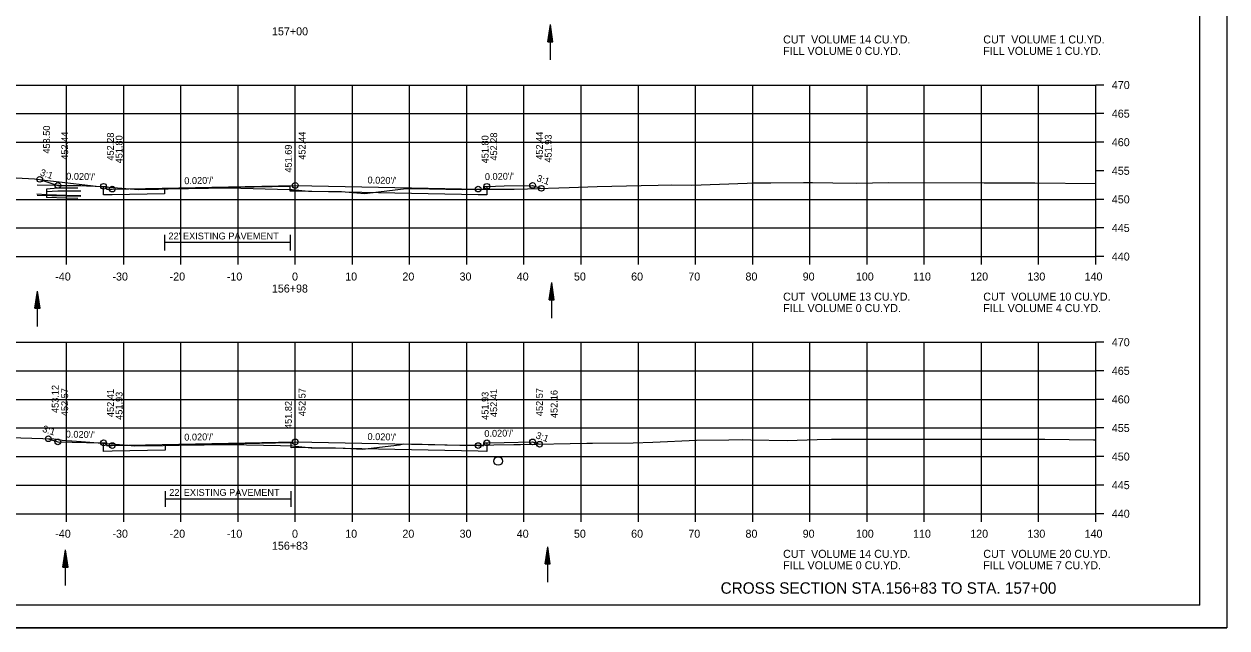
# Model space of a CAD drawing. Extents: x 1538688 to 1540766, y 656250 to 671912.
# Drawn here: x 1538810.8 to 1539021.1, y 666364.8 to 666470.4 of the extents above; entities that cross this region are included whole.
import ezdxf

# ---------------------------------------------------------------- set-up
doc = ezdxf.new("R2010")
doc.units = 0
for name, color, linetype in [('15', 7, 'Continuous'), ('18', 7, 'Continuous'), ('20', 7, 'Continuous'), ('22', 7, 'Continuous'), ('26', 7, 'Continuous'), ('39', 7, 'Continuous'), ('41', 7, 'Continuous'), ('42', 7, 'Continuous'), ('7', 7, 'Continuous'), ('Borings', 7, 'Continuous'), ('Horizontal Alignment', 7, 'Continuous'), ('RipRap', 7, 'Continuous'), ('Wall Heights', 7, 'Continuous')]:
    doc.layers.add(name, color=color, linetype=linetype)

msp = doc.modelspace()

# ---------------------------------------------------------------- linework, layer by layer
at = {"layer": '15'}
for p, q in [((1538902.35, 666467.34), (1538902.8, 666470.34)), ((1538903.25, 666467.34), (1538902.8, 666470.34)), ((1538902.43, 666467.34), (1538902.8, 666469.84)), ((1538902.5, 666467.34), (1538902.8, 666469.33)), ((1538902.58, 666467.34), (1538902.8, 666468.83)), ((1538902.66, 666467.34), (1538902.8, 666468.32)), ((1538903.18, 666467.34), (1538902.8, 666469.84)), ((1538903.1, 666467.34), (1538902.8, 666469.33)), ((1538903.03, 666467.34), (1538902.8, 666468.83)), ((1538902.95, 666467.34), (1538902.8, 666468.32)), ((1538902.35, 666467.34), (1538903.25, 666467.34)), ((1538902.73, 666467.34), (1538902.8, 666467.82)), ((1538902.87, 666467.34), (1538902.8, 666467.82)), ((1538902.58, 666422.2), (1538903.03, 666425.2)), ((1538902.66, 666422.2), (1538903.03, 666424.7)), ((1538902.73, 666422.2), (1538903.03, 666424.18)), ((1538903.48, 666422.2), (1538903.03, 666425.2)), ((1538903.41, 666422.2), (1538903.03, 666424.7)), ((1538903.33, 666422.2), (1538903.03, 666424.18)), ((1538812.67, 666420.73), (1538813.12, 666423.73)), ((1538812.75, 666420.73), (1538813.12, 666423.23)), ((1538812.83, 666420.73), (1538813.12, 666422.71)), ((1538812.9, 666420.73), (1538813.12, 666422.21)), ((1538812.98, 666420.73), (1538813.12, 666421.7)), ((1538813.57, 666420.73), (1538813.12, 666423.73)), ((1538813.5, 666420.73), (1538813.12, 666423.23)), ((1538813.42, 666420.73), (1538813.12, 666422.71)), ((1538813.35, 666420.73), (1538813.12, 666422.21)), ((1538813.27, 666420.73), (1538813.12, 666421.7)), ((1538902.58, 666422.2), (1538903.48, 666422.2)), ((1538902.81, 666422.2), (1538903.03, 666423.68)), ((1538902.89, 666422.2), (1538903.03, 666423.17)), ((1538902.96, 666422.2), (1538903.03, 666422.67)), ((1538903.26, 666422.2), (1538903.03, 666423.68)), ((1538903.18, 666422.2), (1538903.03, 666423.17)), ((1538903.1, 666422.2), (1538903.03, 666422.67)), ((1538812.67, 666420.73), (1538813.57, 666420.73)), ((1538813.05, 666420.73), (1538813.12, 666421.2)), ((1538813.19, 666420.73), (1538813.12, 666421.2)), ((1538817.56, 666375.43), (1538818.01, 666378.43)), ((1538817.64, 666375.43), (1538818.01, 666377.93)), ((1538818.46, 666375.43), (1538818.01, 666378.43)), ((1538818.39, 666375.43), (1538818.01, 666377.93)), ((1538901.89, 666375.98), (1538902.34, 666378.98)), ((1538901.97, 666375.98), (1538902.34, 666378.48)), ((1538902.05, 666375.98), (1538902.34, 666377.96)), ((1538902.79, 666375.98), (1538902.34, 666378.98)), ((1538902.72, 666375.98), (1538902.34, 666378.48)), ((1538902.64, 666375.98), (1538902.34, 666377.96)), ((1538817.56, 666375.43), (1538818.46, 666375.43)), ((1538817.71, 666375.43), (1538818.01, 666377.41)), ((1538817.79, 666375.43), (1538818.01, 666376.91)), ((1538817.87, 666375.43), (1538818.01, 666376.4)), ((1538817.94, 666375.43), (1538818.01, 666375.9)), ((1538818.31, 666375.43), (1538818.01, 666377.41)), ((1538818.23, 666375.43), (1538818.01, 666376.91)), ((1538818.16, 666375.43), (1538818.01, 666376.4)), ((1538818.08, 666375.43), (1538818.01, 666375.9)), ((1538901.89, 666375.98), (1538902.79, 666375.98)), ((1538902.12, 666375.98), (1538902.34, 666377.46)), ((1538902.2, 666375.98), (1538902.34, 666376.95)), ((1538902.27, 666375.98), (1538902.34, 666376.45)), ((1538902.57, 666375.98), (1538902.34, 666377.46)), ((1538902.49, 666375.98), (1538902.34, 666376.95)), ((1538902.42, 666375.98), (1538902.34, 666376.45))]:
    msp.add_line(p, q, dxfattribs=at)
at = {"layer": '18'}
for points in [[(1538809.36, 666443.55), (1538812.56, 666443.39), (1538814.37, 666443.15), (1538819.38, 666442.53), (1538823.38, 666442.09), (1538830.09, 666441.53), (1538830.71, 666441.47), (1538834.26, 666441.58), (1538835.77, 666441.61), (1538835.85, 666441.61), (1538835.96, 666441.62), (1538846.57, 666441.79), (1538857.2, 666441.52), (1538857.63, 666441.51), (1538860.53, 666441.21), (1538860.66, 666441.2), (1538860.85, 666441.2), (1538866.08, 666441.13), (1538866.3, 666441.12), (1538870.31, 666440.81), (1538870.84, 666440.87), (1538877.58, 666441.68), (1538878.75, 666441.65), (1538887.41, 666441.47), (1538889.63, 666441.54), (1538892.89, 666441.54), (1538896.48, 666441.54), (1538898.82, 666441.63), (1538906.1, 666441.84), (1538910.96, 666442.04), (1538918.68, 666442.22), (1538921.65, 666442.28), (1538923.98, 666442.29), (1538927.51, 666442.27), (1538937.2, 666442.6), (1538938.28, 666442.64), (1538939.1, 666442.66), (1538941.35, 666442.68), (1538947.07, 666442.74), (1538948.66, 666442.7), (1538952.2, 666442.68), (1538956.38, 666442.62), (1538961.86, 666442.75), (1538978.65, 666442.68), (1538985.95, 666442.69), (1538987.49, 666442.68), (1538998.18, 666442.55)], [(1538804.34, 666398.25), (1538815.96, 666397.86), (1538817.42, 666397.65), (1538819.1, 666397.5), (1538820.75, 666397.41), (1538828.94, 666396.75), (1538830.04, 666396.65), (1538835.06, 666396.73), (1538835.96, 666396.75), (1538837.86, 666396.77), (1538846.67, 666396.91), (1538855.59, 666396.68), (1538857.72, 666396.64), (1538860.45, 666396.37), (1538860.99, 666396.32), (1538865.22, 666396.27), (1538866.55, 666396.25), (1538866.88, 666396.23), (1538869.97, 666396.08), (1538876.44, 666396.82), (1538877.13, 666396.99), (1538880.39, 666396.93), (1538886.99, 666396.79), (1538890.08, 666396.76), (1538892.94, 666396.8), (1538896.38, 666396.89), (1538897.37, 666396.88), (1538897.56, 666396.86), (1538909.19, 666397.1), (1538910.14, 666397.13), (1538917.27, 666397.16), (1538920.72, 666397.29), (1538928.35, 666397.62), (1538934.01, 666397.71), (1538936.42, 666397.75), (1538937.86, 666397.72), (1538944.2, 666397.6), (1538949.47, 666397.73), (1538951.93, 666397.82), (1538952.57, 666397.82), (1538952.88, 666397.81), (1538953.29, 666397.82), (1538954.54, 666397.82), (1538983.21, 666397.83), (1538989.25, 666397.8), (1538997.76, 666397.7), (1538998.18, 666397.7)]]:
    msp.add_lwpolyline(points, dxfattribs=at)
at = {"layer": '20'}
for points in [[(1538813.5, 666443.27), (1538816.67, 666442.21), (1538821.67, 666442.11), (1538824.67, 666442.05), (1538825.17, 666442.05), (1538825.18, 666441.55), (1538826.18, 666441.57), (1538858.18, 666442.21), (1538890.18, 666441.57), (1538891.18, 666441.55), (1538891.19, 666442.05), (1538891.69, 666442.05), (1538894.69, 666442.11), (1538899.69, 666442.21), (1538901.22, 666441.7)], [(1538815.01, 666397.89), (1538816.67, 666397.34), (1538821.67, 666397.24), (1538824.67, 666397.18), (1538825.17, 666397.18), (1538825.18, 666396.68), (1538826.18, 666396.7), (1538858.18, 666397.34), (1538890.18, 666396.7), (1538891.18, 666396.68), (1538891.19, 666397.18), (1538891.69, 666397.18), (1538894.69, 666397.24), (1538899.69, 666397.34), (1538900.91, 666396.93)]]:
    msp.add_lwpolyline(points, dxfattribs=at)
at = {"layer": '22'}
for p, q in [((1538718.18, 666459.77), (1538998.18, 666459.77)), ((1538818.18, 666429.77), (1538818.18, 666459.77)), ((1538828.18, 666429.77), (1538828.18, 666459.77)), ((1538838.18, 666429.77), (1538838.18, 666459.77)), ((1538848.18, 666429.77), (1538848.18, 666459.77)), ((1538858.18, 666429.77), (1538858.18, 666459.77)), ((1538868.18, 666429.77), (1538868.18, 666459.77)), ((1538878.18, 666429.77), (1538878.18, 666459.77)), ((1538888.18, 666429.77), (1538888.18, 666459.77)), ((1538898.18, 666429.77), (1538898.18, 666459.77)), ((1538908.18, 666429.77), (1538908.18, 666459.77)), ((1538918.18, 666429.77), (1538918.18, 666459.77)), ((1538928.18, 666429.77), (1538928.18, 666459.77)), ((1538938.18, 666429.77), (1538938.18, 666459.77)), ((1538948.18, 666429.77), (1538948.18, 666459.77)), ((1538958.18, 666429.77), (1538958.18, 666459.77)), ((1538968.18, 666429.77), (1538968.18, 666459.77)), ((1538978.18, 666429.77), (1538978.18, 666459.77)), ((1538988.18, 666429.77), (1538988.18, 666459.77)), ((1538998.18, 666429.77), (1538998.18, 666459.77)), ((1538718.18, 666454.77), (1538998.18, 666454.77)), ((1538718.18, 666449.77), (1538998.18, 666449.77)), ((1538718.18, 666439.77), (1538998.18, 666439.77)), ((1538718.18, 666434.77), (1538998.18, 666434.77)), ((1538718.18, 666429.77), (1538998.18, 666429.77)), ((1538718.18, 666414.77), (1538998.18, 666414.77)), ((1538818.18, 666384.77), (1538818.18, 666414.77)), ((1538828.18, 666384.77), (1538828.18, 666414.77)), ((1538838.18, 666384.77), (1538838.18, 666414.77)), ((1538848.18, 666384.77), (1538848.18, 666414.77)), ((1538858.18, 666384.77), (1538858.18, 666414.77)), ((1538868.18, 666384.77), (1538868.18, 666414.77)), ((1538878.18, 666384.77), (1538878.18, 666414.77)), ((1538888.18, 666384.77), (1538888.18, 666414.77)), ((1538898.18, 666384.77), (1538898.18, 666414.77)), ((1538908.18, 666384.77), (1538908.18, 666414.77)), ((1538918.18, 666384.77), (1538918.18, 666414.77)), ((1538928.18, 666384.77), (1538928.18, 666414.77)), ((1538938.18, 666384.77), (1538938.18, 666414.77)), ((1538948.18, 666384.77), (1538948.18, 666414.77)), ((1538958.18, 666384.77), (1538958.18, 666414.77)), ((1538968.18, 666384.77), (1538968.18, 666414.77)), ((1538978.18, 666384.77), (1538978.18, 666414.77)), ((1538988.18, 666384.77), (1538988.18, 666414.77)), ((1538998.18, 666384.77), (1538998.18, 666414.77)), ((1538718.18, 666409.77), (1538998.18, 666409.77)), ((1538718.18, 666404.77), (1538998.18, 666404.77)), ((1538718.18, 666399.77), (1538998.18, 666399.77)), ((1538718.18, 666394.77), (1538998.18, 666394.77)), ((1538718.18, 666389.77), (1538998.18, 666389.77)), ((1538718.18, 666384.77), (1538998.18, 666384.77))]:
    msp.add_line(p, q, dxfattribs=at)
at = {"layer": '26'}
for p, q in [((1538813.03, 666442.33), (1538820.68, 666442.18)), ((1538816.69, 666441.73), (1538814.69, 666441.58)), ((1538814.69, 666441.58), (1538814.69, 666440.08)), ((1538816.67, 666441.23), (1538814.69, 666441.08)), ((1538813.03, 666440.5), (1538820.68, 666440.35)), ((1538687.78, 666364.79), (1539021.11, 666364.79))]:
    msp.add_line(p, q, dxfattribs=at)
msp.add_lwpolyline([(1538687.77, 666578.12), (1539021.11, 666578.12), (1539021.11, 666364.78), (1538687.77, 666364.78)], close=True, dxfattribs=at)
for points in [[(1538820.68, 666440.4), (1538818.25, 666440.47), (1538814.69, 666440.58), (1538812.99, 666440.67)], [(1538820.18, 666441.73), (1538818.18, 666441.73), (1538816.67, 666441.73)], [(1538820.68, 666441.23), (1538818.18, 666441.23), (1538816.67, 666441.23)], [(1538820.18, 666439.91), (1538818.24, 666439.97), (1538814.69, 666440.08)]]:
    msp.add_lwpolyline(points, dxfattribs=at)
for centre in [(1538813.5, 666443.27), (1538816.67, 666442.21), (1538824.67, 666442.05), (1538826.18, 666441.57), (1538858.18, 666442.21), (1538890.18, 666441.57), (1538891.69, 666442.05), (1538899.69, 666442.21), (1538901.22, 666441.7), (1538815.01, 666397.89), (1538816.67, 666397.34), (1538824.67, 666397.18), (1538826.18, 666396.7), (1538858.18, 666397.34), (1538890.18, 666396.7), (1538891.69, 666397.18), (1538899.69, 666397.34), (1538900.91, 666396.93)]:
    msp.add_circle(centre, 0.5, dxfattribs=at)
at = {"layer": '39'}
for p, q in [((1538902.8, 666464.16), (1538902.8, 666470.34)), ((1538903.03, 666419.01), (1538903.03, 666425.2)), ((1538813.12, 666417.54), (1538813.12, 666423.73)), ((1538818.01, 666372.24), (1538818.01, 666378.43)), ((1538902.34, 666372.79), (1538902.34, 666378.98))]:
    msp.add_line(p, q, dxfattribs=at)
msp.add_circle((1538893.68, 666393.99), 0.75, dxfattribs=at)
at = {"layer": '7'}
for p, q in [((1538835.31, 666433.57), (1538835.31, 666430.83)), ((1538857.31, 666433.57), (1538857.31, 666430.83)), ((1538857.31, 666432.2), (1538835.31, 666432.2)), ((1538835.44, 666388.7), (1538835.44, 666385.96)), ((1538857.44, 666388.7), (1538857.44, 666385.96)), ((1538857.44, 666387.33), (1538835.44, 666387.33))]:
    msp.add_line(p, q, dxfattribs=at)
at = {"layer": 'Borings'}
for p, q in [((1538998.18, 666429.77), (1538998.18, 666459.77)), ((1538999.58, 666459.77), (1538998.18, 666459.77)), ((1538999.58, 666454.77), (1538998.18, 666454.77)), ((1538999.58, 666449.77), (1538998.18, 666449.77)), ((1538999.58, 666444.77), (1538998.18, 666444.77)), ((1538999.58, 666439.77), (1538998.18, 666439.77)), ((1538999.58, 666434.77), (1538998.18, 666434.77)), ((1538718.18, 666429.77), (1538998.18, 666429.77)), ((1538818.18, 666428.37), (1538818.18, 666429.77)), ((1538828.18, 666428.37), (1538828.18, 666429.77)), ((1538838.18, 666428.37), (1538838.18, 666429.77)), ((1538848.18, 666428.37), (1538848.18, 666429.77)), ((1538858.18, 666428.37), (1538858.18, 666429.77)), ((1538868.18, 666428.37), (1538868.18, 666429.77)), ((1538878.18, 666428.37), (1538878.18, 666429.77)), ((1538888.18, 666428.37), (1538888.18, 666429.77)), ((1538898.18, 666428.37), (1538898.18, 666429.77)), ((1538908.18, 666428.37), (1538908.18, 666429.77)), ((1538918.18, 666428.37), (1538918.18, 666429.77)), ((1538928.18, 666428.37), (1538928.18, 666429.77)), ((1538938.18, 666428.37), (1538938.18, 666429.77)), ((1538948.18, 666428.37), (1538948.18, 666429.77)), ((1538958.18, 666428.37), (1538958.18, 666429.77)), ((1538968.18, 666428.37), (1538968.18, 666429.77)), ((1538978.18, 666428.37), (1538978.18, 666429.77)), ((1538988.18, 666428.37), (1538988.18, 666429.77)), ((1538998.18, 666428.37), (1538998.18, 666429.77)), ((1538999.58, 666429.77), (1538998.18, 666429.77)), ((1538998.18, 666384.77), (1538998.18, 666414.77)), ((1538999.58, 666414.77), (1538998.18, 666414.77)), ((1538999.58, 666409.77), (1538998.18, 666409.77)), ((1538999.58, 666404.77), (1538998.18, 666404.77)), ((1538999.58, 666399.77), (1538998.18, 666399.77)), ((1538999.58, 666394.77), (1538998.18, 666394.77)), ((1538999.58, 666389.77), (1538998.18, 666389.77)), ((1538718.18, 666384.77), (1538998.18, 666384.77)), ((1538818.18, 666383.37), (1538818.18, 666384.77)), ((1538828.18, 666383.37), (1538828.18, 666384.77)), ((1538838.18, 666383.37), (1538838.18, 666384.77)), ((1538848.18, 666383.37), (1538848.18, 666384.77)), ((1538858.18, 666383.37), (1538858.18, 666384.77)), ((1538868.18, 666383.37), (1538868.18, 666384.77)), ((1538878.18, 666383.37), (1538878.18, 666384.77)), ((1538888.18, 666383.37), (1538888.18, 666384.77)), ((1538898.18, 666383.37), (1538898.18, 666384.77)), ((1538908.18, 666383.37), (1538908.18, 666384.77)), ((1538918.18, 666383.37), (1538918.18, 666384.77)), ((1538928.18, 666383.37), (1538928.18, 666384.77)), ((1538938.18, 666383.37), (1538938.18, 666384.77)), ((1538948.18, 666383.37), (1538948.18, 666384.77)), ((1538958.18, 666383.37), (1538958.18, 666384.77)), ((1538968.18, 666383.37), (1538968.18, 666384.77)), ((1538978.18, 666383.37), (1538978.18, 666384.77)), ((1538988.18, 666383.37), (1538988.18, 666384.77)), ((1538998.18, 666383.37), (1538998.18, 666384.77)), ((1538999.58, 666384.77), (1538998.18, 666384.77))]:
    msp.add_line(p, q, dxfattribs=at)
at = {"layer": 'RipRap'}
for q in [(1539016.36, 666574.23), (1538700.18, 666368.77)]:
    msp.add_line((1539016.36, 666368.77), q, dxfattribs=at)
at = {"layer": 'Wall Heights'}
for points in [[(1538891.69, 666442.05), (1538891.69, 666440.55), (1538890.18, 666440.57), (1538858.18, 666441.21), (1538857.31, 666441.19), (1538857.31, 666442.03), (1538835.31, 666441.59), (1538835.31, 666440.75), (1538826.18, 666440.57), (1538824.67, 666440.55), (1538824.67, 666442.05)], [(1538891.69, 666397.18), (1538891.69, 666395.68), (1538890.18, 666395.7), (1538858.18, 666396.34), (1538857.45, 666396.32), (1538857.45, 666397.15), (1538835.45, 666396.71), (1538835.45, 666395.88), (1538826.18, 666395.7), (1538824.67, 666395.68), (1538824.67, 666397.18)]]:
    msp.add_lwpolyline(points, dxfattribs=at)

# ---------------------------------------------------------------- texts
at = {"layer": '15'}
msp.add_text('CROSS SECTION STA.156+83 TO STA. 157+00', height=2, dxfattribs=at).set_placement((1538932.57, 666370.77))
at = {"layer": '41'}
for s, p in [('453.50', (1538815.3, 666447.77)), ('452.44', (1538818.47, 666446.71)), ('452.28', (1538826.47, 666446.55)), ('452.44', (1538859.98, 666446.71)), ('452.28', (1538893.49, 666446.55)), ('452.44', (1538901.49, 666446.71)), ('451.80', (1538827.98, 666446.07)), ('451.69', (1538857.58, 666444.45)), ('451.80', (1538891.98, 666446.07)), ('451.93', (1538903.02, 666446.2)), ('453.12', (1538816.81, 666402.39)), ('452.57', (1538818.47, 666401.84)), ('452.41', (1538826.47, 666401.68)), ('451.93', (1538827.98, 666401.2)), ('452.57', (1538859.98, 666401.84)), ('451.93', (1538891.98, 666401.2)), ('452.41', (1538893.49, 666401.68)), ('452.57', (1538901.49, 666401.84)), ('452.16', (1538904.05, 666401.51)), ('451.82', (1538857.58, 666399.59))]:
    msp.add_text(s, height=1.2, rotation=90, dxfattribs=at).set_placement(p)
at = {"layer": '42'}
for s, rotation, p in [('3:1', 341.5651, (1538813.47, 666443.99)), ("0.020'/'", 358.8542, (1538818.12, 666443.23)), ("0.020'/'", 1.1458, (1538838.79, 666442.42)), ("0.020'/'", 358.8542, (1538870.81, 666442.56)), ("0.020'/'", 1.1458, (1538891.36, 666443.14)), ('3:1', 341.5651, (1538900.31, 666442.98)), ('3:1', 341.5651, (1538813.87, 666399.14)), ("0.020'/'", 358.8542, (1538818.04, 666398.1)), ("0.020'/'", 1.1458, (1538838.79, 666397.55)), ("0.020'/'", 358.8542, (1538870.81, 666397.68)), ("0.020'/'", 1.1458, (1538891.26, 666398.2)), ('3:1', 341.5651, (1538900.16, 666397.99))]:
    msp.add_text(s, height=1.2, rotation=rotation, dxfattribs=at).set_placement(p)
at = {"layer": '7'}
for p in [(1538836.01, 666432.76), (1538836.15, 666387.89)]:
    msp.add_text("22' EXISTING PAVEMENT", height=1.2, dxfattribs=at).set_placement(p)
at = {"layer": 'Horizontal Alignment'}
for s, p in [('157+00', (1538854.12, 666468.47)), ('CUT  VOLUME 14 CU.YD.', (1538943.5, 666467.05)), ('CUT  VOLUME 1 CU.YD.', (1538978.5, 666467.05)), ('FILL VOLUME 0 CU.YD.', (1538943.5, 666465.05)), ('FILL VOLUME 1 CU.YD.', (1538978.5, 666465.05)), ('470', (1539000.98, 666459.07)), ('465', (1539000.98, 666454.07)), ('460', (1539000.98, 666449.07)), ('455', (1539000.98, 666444.07)), ('450', (1539000.98, 666439.07)), ('445', (1539000.98, 666434.07)), ('440', (1539000.98, 666429.07)), ('-40', (1538816.22, 666425.57)), ('-30', (1538826.22, 666425.57)), ('-20', (1538836.22, 666425.57)), ('-10', (1538846.22, 666425.57)), ('0', (1538857.62, 666425.57)), ('10', (1538866.92, 666425.57)), ('20', (1538876.92, 666425.57)), ('30', (1538886.92, 666425.57)), ('40', (1538896.92, 666425.57)), ('50', (1538906.92, 666425.57)), ('60', (1538916.92, 666425.57)), ('70', (1538926.92, 666425.57)), ('80', (1538936.92, 666425.57)), ('90', (1538946.92, 666425.57)), ('100', (1538956.22, 666425.57)), ('110', (1538966.22, 666425.57)), ('120', (1538976.22, 666425.57)), ('130', (1538986.22, 666425.57)), ('140', (1538996.22, 666425.57)), ('156+98', (1538854.1, 666423.47)), ('CUT  VOLUME 13 CU.YD.', (1538943.5, 666422.05)), ('CUT  VOLUME 10 CU.YD.', (1538978.5, 666422.05)), ('FILL VOLUME 0 CU.YD.', (1538943.5, 666420.05)), ('FILL VOLUME 4 CU.YD.', (1538978.5, 666420.05)), ('470', (1539000.98, 666414.07)), ('465', (1539000.98, 666409.07)), ('460', (1539000.98, 666404.07)), ('455', (1539000.98, 666399.07)), ('450', (1539000.98, 666394.07)), ('445', (1539000.98, 666389.07)), ('440', (1539000.98, 666384.07)), ('-40', (1538816.22, 666380.57)), ('-30', (1538826.22, 666380.57)), ('-20', (1538836.22, 666380.57)), ('-10', (1538846.22, 666380.57)), ('0', (1538857.62, 666380.57)), ('10', (1538866.92, 666380.57)), ('20', (1538876.92, 666380.57)), ('30', (1538886.92, 666380.57)), ('40', (1538896.92, 666380.57)), ('50', (1538906.92, 666380.57)), ('60', (1538916.92, 666380.57)), ('70', (1538926.92, 666380.57)), ('80', (1538936.92, 666380.57)), ('90', (1538946.92, 666380.57)), ('100', (1538956.22, 666380.57)), ('110', (1538966.22, 666380.57)), ('120', (1538976.22, 666380.57)), ('130', (1538986.22, 666380.57)), ('140', (1538996.22, 666380.57)), ('156+83', (1538854.11, 666378.47)), ('CUT  VOLUME 14 CU.YD.', (1538943.5, 666377.05)), ('CUT  VOLUME 20 CU.YD.', (1538978.5, 666377.05)), ('FILL VOLUME 0 CU.YD.', (1538943.5, 666375.05)), ('FILL VOLUME 7 CU.YD.', (1538978.5, 666375.05))]:
    msp.add_text(s, height=1.4, dxfattribs=at).set_placement(p)

doc.saveas('drawing.dxf')
